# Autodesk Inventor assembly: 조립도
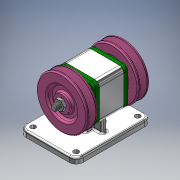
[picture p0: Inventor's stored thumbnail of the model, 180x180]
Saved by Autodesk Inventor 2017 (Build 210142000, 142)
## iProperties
Part Number: 조립도
Material: 일반
Document SubType Name: Assembly
Designer: 00-00
Author: 00-00
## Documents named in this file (10)
- C:\Users\00-00\Desktop\701106v1041\답안조립도.iam
- C:\Users\00-00\Desktop\701106v1041\본체.ipt
- C:\Users\00-00\Desktop\701106v1041\V-벨트풀리.ipt
- C:\Users\00-00\Desktop\701106v1041\너트 M10x1.ipt
- C:\Users\00-00\Desktop\701106v1041\베어링 6004.ipt
- C:\Users\00-00\Desktop\701106v1041\볼트 M4.ipt
- C:\Users\00-00\Desktop\701106v1041\오일 실 17 30 5.ipt
- C:\Users\00-00\Desktop\701106v1041\축.ipt
- C:\Users\00-00\Desktop\701106v1041\커버.ipt
- C:\Users\00-00\Desktop\701106v1041\키 5 x 5 x 12.ipt
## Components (2 placed, 1 different names)
1. V-벨트풀리:1
2. V-벨트풀리:2
## Component patterns: 구성요소 패턴 1:2 (2 elements), 구성요소 패턴 3:2 (2 elements)
